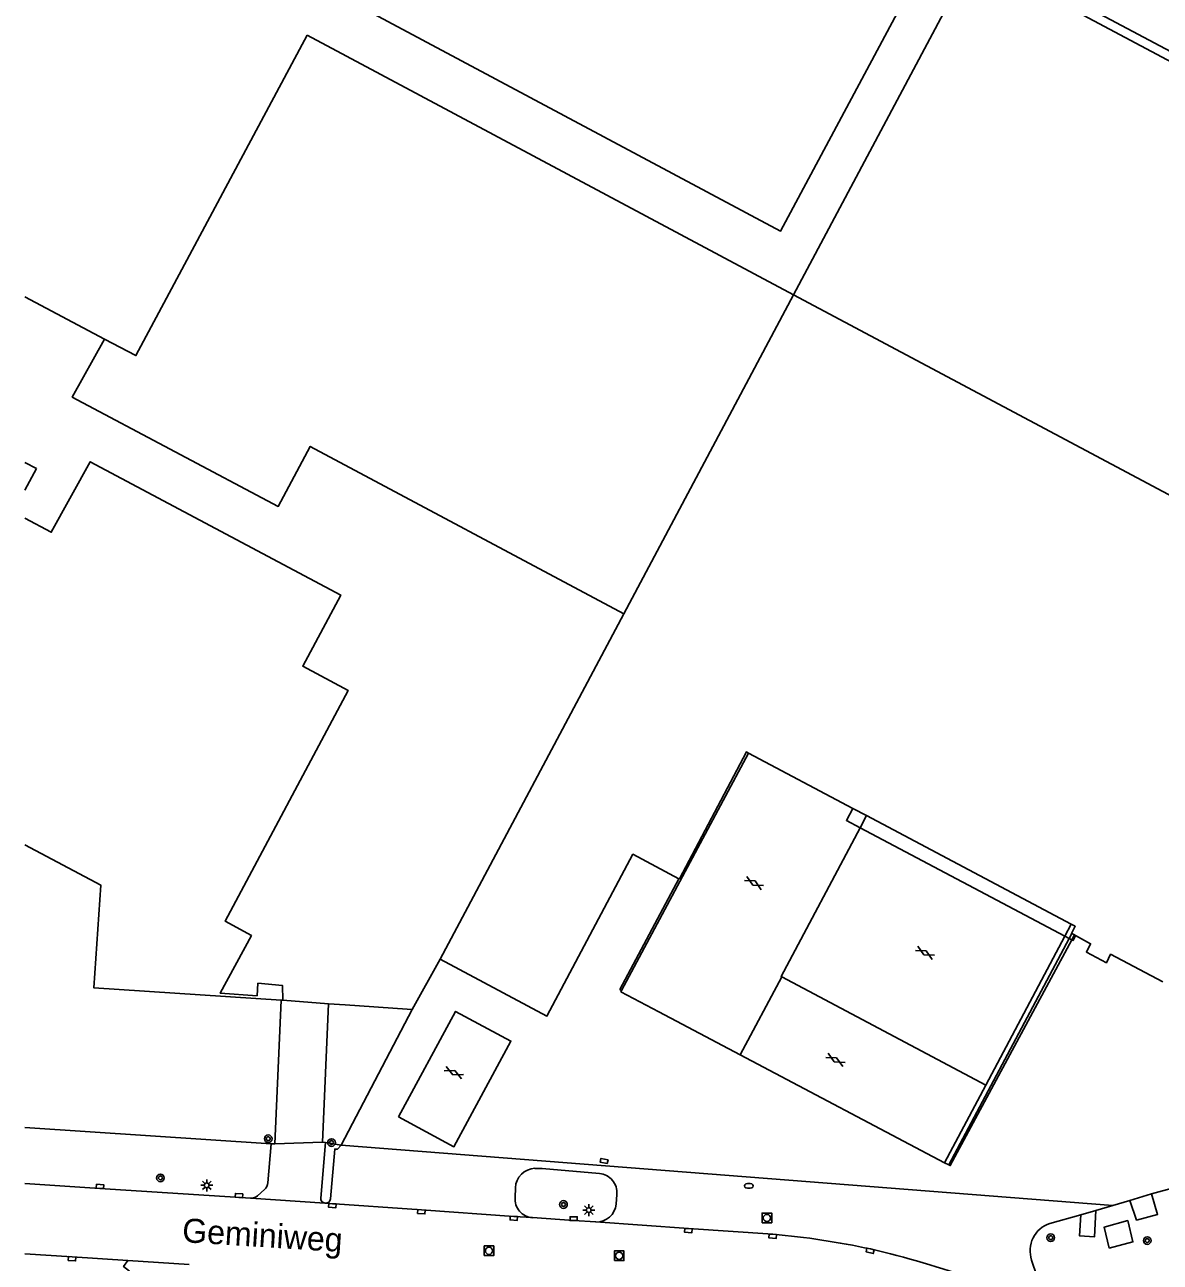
# Model space of a CAD drawing. Extents: x 135999 to 138000, y 396000 to 398501.
# Drawn here: x 136000 to 136118.3, y 398023.9 to 398152.8 of the extents above; entities that cross this region are included whole.
import ezdxf

# ---------------------------------------------------------------- set-up
doc = ezdxf.new("R2010")
doc.units = 0
for name, color, linetype in [('gg-afsc-erfafscheiding', 7, 'Continuous'), ('gg-afsc-hekwerk', 7, 'Continuous'), ('gg-afsc-muur', 7, 'Continuous'), ('gg-anno-openbare ruimte label', 7, 'Continuous'), ('gg-bbg-bijgebouw', 7, 'Continuous'), ('gg-bbg-hoofdgebouw', 7, 'Continuous'), ('gg-bbg-onder overbouw', 7, 'Continuous'), ('gg-bbg-pand overbouw', 7, 'Continuous'), ('gg-bbg-tussenscheiding', 7, 'Continuous'), ('gg-knt-verharding', 7, 'Continuous'), ('gg-knt-verharding nz', 7, 'Continuous'), ('gg-kwrk-keermuur', 7, 'Continuous'), ('gt-grn-groengrens', 7, 'Continuous'), ('gt-grn-vlakafsluiter', 7, 'Continuous'), ('gt-symb-boom', 7, 'Continuous'), ('gt-symb-brandkraan', 7, 'Continuous'), ('gt-symb-gesloten verharding', 7, 'Continuous'), ('gt-symb-kolk', 7, 'Continuous'), ('gt-symb-kolk center center', 7, 'Continuous'), ('gt-symb-lichtmast', 7, 'Continuous'), ('gt-symb-rioolschacht', 7, 'Continuous')]:
    doc.layers.add(name, color=color, linetype=linetype)

# ---------------------------------------------------------------- blocks, each defined once
blk = doc.blocks.new('gt0-BOOM')
at = {"layer": 'gt-symb-boom'}
for radius in [0.4, 0.2]:
    blk.add_circle((0, 0), radius, dxfattribs=at)
blk = doc.blocks.new('gt0-KOLK')
at = {"layer": 'gt-symb-kolk'}
blk.add_lwpolyline([(0, 0), (0.38, 0), (0.38, 0.4), (-0.38, 0.4), (-0.38, 0), (0, 0)], dxfattribs=at)
blk = doc.blocks.new('gt0-GESVH1')
at = {"layer": 'gt-symb-gesloten verharding'}
for p, q in [((-0.99, -0.26), (0.01, 0.24)), ((0.01, -0.26), (-0.99, 0.24)), ((0.01, 0.24), (1.01, -0.26)), ((1.01, 0.24), (0.01, -0.26))]:
    blk.add_line(p, q, dxfattribs=at)
blk = doc.blocks.new('gt0-BR')
at = {"layer": 'gt-symb-brandkraan'}
for centre, radius, start, end in [((-0.24, 0), 0.206, 107.5669, 252.4331), ((0.6, -2.66), 3, 106.892, 107.5669), ((0, -0.69), 0.938, 73.108, 106.892), ((-0.6, -2.66), 3, 72.4331, 73.108), ((0.24, 0), 0.206, 287.567, 72.4331), ((0.6, 2.66), 3, 252.4331, 253.108), ((0, 0.69), 0.938, 253.108, 286.8921), ((-0.6, 2.66), 3, 286.8921, 287.567)]:
    blk.add_arc(centre, radius, start, end, dxfattribs=at)
blk = doc.blocks.new('gt0-KOLKCC')
at = {"layer": 'gt-symb-kolk center center'}
blk.add_lwpolyline([(-0.38, 0.2), (0.38, 0.2), (0.38, -0.2), (-0.38, -0.2)], close=True, dxfattribs=at)
blk = doc.blocks.new('gt0-LMAST')
at = {"layer": 'gt-symb-lichtmast'}
for p, q in [((-0.18, 0.17), (-0.45, 0.44)), ((-0.01, 0.25), (-0.01, 0.62)), ((0.17, 0.17), (0.44, 0.44)), ((-0.26, 0), (-0.63, 0)), ((-0.18, -0.18), (-0.45, -0.45)), ((-0.01, -0.25), (-0.01, -0.63)), ((0.44, -0.45), (0.17, -0.18)), ((0.24, 0), (0.62, 0))]:
    blk.add_line(p, q, dxfattribs=at)
blk.add_circle((-0.01, 0), 0.25, dxfattribs=at)
blk = doc.blocks.new('gt0-RS')
at = {"layer": 'gt-symb-rioolschacht'}
blk.add_lwpolyline([(-0.5, -0.5), (0.5, -0.5), (0.5, 0.5), (-0.5, 0.5)], close=True, dxfattribs=at)
blk.add_circle((0, 0), 0.375, dxfattribs=at)

msp = doc.modelspace()

# ---------------------------------------------------------------- linework, layer by layer
at = {"layer": 'gg-afsc-erfafscheiding'}
for p, q in [((136026.05, 398036.21), (136031.02, 398036.38)), ((136113.33, 398029.79), (136032.96, 398036.09))]:
    msp.add_line(p, q, dxfattribs=at)
at = {"layer": 'gg-afsc-hekwerk'}
msp.add_line((136000, 398124.44), (136008.29, 398120.05), dxfattribs=at)
at = {"layer": 'gg-afsc-muur'}
for p, q in [((136040.34, 398050.21), (136043.28, 398055.46)), ((136026.88, 398051.18), (136031.64, 398050.82)), ((136031.64, 398050.82), (136033.38, 398050.7)), ((136033.38, 398050.7), (136039.82, 398050.25)), ((136039.82, 398050.25), (136040.34, 398050.21))]:
    msp.add_line(p, q, dxfattribs=at)
at = {"layer": 'gg-bbg-bijgebouw'}
msp.add_line((136029.4, 398151.72), (136080.08, 398124.65), dxfattribs=at)
for points in [[(136080.08, 398124.65), (136098.81, 398159.9), (136158.21, 398128.28)], [(136008.29, 398120.05), (136011.57, 398118.33), (136029.4, 398151.72)], [(136062.39, 398091.42), (136029.73, 398108.87), (136026.41, 398102.62), (136004.95, 398114.02), (136008.29, 398120.05)]]:
    msp.add_lwpolyline(points, dxfattribs=at)
at = {"layer": 'gg-bbg-hoofdgebouw'}
for p, q in [((136000, 398107.21), (136001.21, 398106.56)), ((136000, 398104.33), (136001.21, 398106.56)), ((136043.28, 398055.46), (136062.39, 398091.42)), ((136086.24, 398071.17), (136075.37, 398076.93)), ((136026.72, 398051.19), (136026.88, 398051.18))]:
    msp.add_line(p, q, dxfattribs=at)
for points in [[(136037, 398187.29), (136092.74, 398157.55), (136078.71, 398131.29), (136023, 398161.08)], [(136177.55, 398164.23), (136167.76, 398145.6), (136164.15, 398147.56), (136155.32, 398130.9), (136084.58, 398168.48)], [(136000, 398101.4), (136002.76, 398099.93), (136006.83, 398107.28), (136032.91, 398093.38), (136028.95, 398085.97), (136033.68, 398083.45), (136020.86, 398059.43), (136023.61, 398057.92), (136020.36, 398051.9), (136024.2, 398051.64), (136024.29, 398052.95), (136026.83, 398052.73), (136026.88, 398051.18)], [(136075.37, 398076.93), (136075.17, 398077.04), (136068.18, 398063.81), (136068.14, 398063.83)], [(136000, 398067.38), (136007.91, 398063.17), (136007.2, 398052.47), (136026.72, 398051.19)], [(136068.14, 398063.83), (136063.34, 398066.39), (136054.38, 398049.53), (136043.28, 398055.46)], [(136118.54, 398053.1), (136113.1, 398055.97), (136112.65, 398055.09), (136110.57, 398056.19), (136111.01, 398057.07), (136109.45, 398057.91)]]:
    msp.add_lwpolyline(points, dxfattribs=at)
at = {"layer": 'gg-bbg-onder overbouw'}
for p, q in [((136087.67, 398070.41), (136086.24, 398071.17)), ((136108.99, 398059.11), (136087.67, 398070.41)), ((136109.32, 398057.98), (136109.05, 398058.12)), ((136109.45, 398057.91), (136109.32, 398057.98))]:
    msp.add_line(p, q, dxfattribs=at)
msp.add_lwpolyline([(136109.05, 398058.12), (136109.02, 398058.14), (136109.42, 398058.88), (136108.99, 398059.11)], dxfattribs=at)
at = {"layer": 'gg-bbg-pand overbouw'}
for p, q in [((136087, 398069.15), (136108.33, 398057.85)), ((136108.33, 398057.85), (136108.78, 398057.61)), ((136108.78, 398057.61), (136109.05, 398057.47))]:
    msp.add_line(p, q, dxfattribs=at)
for points in [[(136086.24, 398071.17), (136085.57, 398069.91), (136087, 398069.15)], [(136109.05, 398057.47), (136109.18, 398057.4), (136109.45, 398057.91)]]:
    msp.add_lwpolyline(points, dxfattribs=at)
at = {"layer": 'gg-bbg-tussenscheiding'}
for p, q in [((136062.39, 398091.42), (136080.08, 398124.65)), ((136080.08, 398124.65), (136139.66, 398092.93))]:
    msp.add_line(p, q, dxfattribs=at)
at = {"layer": 'gg-knt-verharding'}
for p, q in [((136108.33, 398057.85), (136108.99, 398059.11)), ((136100.1, 398042.33), (136108.33, 398057.85)), ((136026.05, 398036.21), (136026.72, 398051.19)), ((136031.64, 398050.82), (136031.02, 398036.38)), ((136032.96, 398036.09), (136040.34, 398050.21)), ((136074.51, 398045.5), (136095.79, 398034.24)), ((136095.79, 398034.24), (136100.1, 398042.33)), ((136031.32, 398036.35), (136030.83, 398030.56)), ((136031.02, 398036.38), (136031.32, 398036.35)), ((136025.31, 398032.16), (136025.65, 398036.23)), ((136025.65, 398036.23), (136026.05, 398036.21)), ((136095.79, 398034.24), (136096.23, 398034.04)), ((136024.24, 398030.82), (136024.98, 398031.47)), ((136051.08, 398030.64), (136051.11, 398031.63)), ((136117.36, 398031.01), (136119.77, 398031.68)), ((136023.53, 398030.55), (136031.27, 398030.04)), ((136031.3, 398030.03), (136031.27, 398030.04)), ((136061.67, 398030.94), (136061.58, 398029.93)), ((136113.33, 398029.79), (136115.09, 398030.3)), ((136117.36, 398031.01), (136115.09, 398030.3)), ((136106.76, 398027.93), (136110.01, 398028.84)), ((136111.57, 398029.27), (136110.01, 398028.84)), ((136111.57, 398029.27), (136113.33, 398029.79)), ((136010.74, 398024.07), (136017.13, 398023.65)), ((136106.48, 398019.36), (136104.87, 398024.11))]:
    msp.add_line(p, q, dxfattribs=at)
for points in [[(136074.51, 398045.5), (136066.03, 398049.97), (136062.1, 398052.07), (136062.17, 398052.21)], [(136038.93, 398039.02), (136044.7, 398035.92), (136050.64, 398046.92), (136044.87, 398050.02), (136038.93, 398039.02)], [(136031.84, 398030.49), (136032.28, 398035.68), (136032.58, 398035.67), (136032.96, 398036.09)], [(136053.14, 398033.66), (136053.89, 398033.65), (136059.86, 398033.12)], [(136000, 398032.08), (136007.83, 398031.58), (136023.53, 398030.55)], [(136031.3, 398030.03), (136041.32, 398029.34), (136050.95, 398028.66), (136052.88, 398028.53)], [(136115.09, 398030.3), (136115.8, 398028.27), (136117.99, 398028.87), (136117.36, 398031.01)], [(136110.01, 398028.84), (136109.87, 398026.62), (136111.43, 398026.54), (136111.57, 398029.27)], [(136052.88, 398028.53), (136057.17, 398028.23), (136059.49, 398028.08)], [(136059.49, 398028.08), (136069.13, 398027.39), (136077.92, 398026.8)], [(136112.96, 398025.34), (136112.43, 398027.55), (136114.88, 398028.23), (136115.41, 398026.01), (136112.96, 398025.34)], [(136000, 398024.77), (136004.94, 398024.45), (136010.74, 398024.07)], [(136010.74, 398024.07), (136010.3, 398023.44), (136010.9, 398022.95), (136010.83, 398022.48)]]:
    msp.add_lwpolyline(points, dxfattribs=at)
for centre, radius, start, end in [((136053.23, 398031.54), 2.13, 92.61, 177.4183), ((136059.7, 398031.16), 1.97, 353.8366, 85.474), ((136024.23, 398032.26), 1.09, 313.3448, 354.8537), ((136023.55, 398031.59), 1.04, 268.8415, 312.06), ((136031.32, 398030.53), 0.493, 175.623, 264.772), ((136031.33, 398030.54), 0.509, 266.2749, 353.8156), ((136053.02, 398030.47), 1.95, 175.1729, 265.783), ((136059.54, 398030.13), 2.06, 268.6287, 354.4174), ((136107.72, 398025.08), 3.01, 108.5979, 198.7895), ((136070.92, 397945.66), 81.44, 77.829, 85.0676), ((136062.69, 397918.38), 109.87, 70.7185, 76.6324)]:
    msp.add_arc(centre, radius, start, end, dxfattribs=at)
at = {"layer": 'gg-knt-verharding nz'}
for p, q in [((136087, 398069.15), (136087.67, 398070.41)), ((136074.51, 398045.5), (136078.85, 398053.63)), ((136078.85, 398053.63), (136100.1, 398042.33))]:
    msp.add_line(p, q, dxfattribs=at)
msp.add_lwpolyline([(136078.85, 398053.63), (136078.78, 398053.65), (136087, 398069.15)], dxfattribs=at)
at = {"layer": 'gg-kwrk-keermuur'}
for p, q in [((136075.37, 398076.93), (136062.17, 398052.21)), ((136108.78, 398057.61), (136096.23, 398034.04)), ((136109.05, 398058.12), (136108.78, 398057.61)), ((136109.05, 398057.47), (136109.32, 398057.98))]:
    msp.add_line(p, q, dxfattribs=at)
for points in [[(136062.17, 398052.21), (136061.99, 398052.3), (136068.14, 398063.83)], [(136096.23, 398034.04), (136096.4, 398033.95), (136109.05, 398057.47)]]:
    msp.add_lwpolyline(points, dxfattribs=at)
at = {"layer": 'gt-grn-groengrens'}
msp.add_line((136031.32, 398036.35), (136032.96, 398036.09), dxfattribs=at)
at = {"layer": 'gt-grn-vlakafsluiter'}
msp.add_line((136000, 398037.93), (136025.65, 398036.23), dxfattribs=at)

# ---------------------------------------------------------------- block references
at = {"layer": 'gt-symb-boom'}
for p in [(136025.36, 398036.75), (136031.95, 398036.35), (136014.13, 398032.67), (136056.11, 398029.9), (136106.86, 398026.44), (136116.91, 398026.14)]:
    msp.add_blockref('gt0-BOOM', p, dxfattribs=at)
at = {"layer": 'gt-symb-brandkraan'}
msp.add_blockref('gt0-BR', (136075.41, 398031.84), dxfattribs=at)
at = {"layer": 'gt-symb-gesloten verharding'}
for p, rotation in [((136075.95, 398063.4), -28.487007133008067), ((136093.76, 398056.13), -28.487007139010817), ((136084.43, 398044.98), -28.48700713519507), ((136044.68, 398043.65), -24.89920052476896)]:
    msp.add_blockref('gt0-GESVH1', p, dxfattribs=dict(at, rotation=rotation))
at = {"layer": 'gt-symb-kolk'}
for p, rotation in [((136007.83, 398031.58), -3.4238023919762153), ((136022.3, 398030.63), -3.4238023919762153), ((136032.05, 398029.98), 176.05870043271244), ((136041.32, 398029.34), 176.05870043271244), ((136050.95, 398028.66), 176.05870043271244), ((136069.13, 398027.39), 176.0587004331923), ((136077.92, 398026.8), 176.05870043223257), ((136088.09, 398025.27), 166.52937593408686), ((136004.94, 398024.45), 176.26107557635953)]:
    msp.add_blockref('gt0-KOLK', p, dxfattribs=dict(at, rotation=rotation))
msp.add_blockref('gt0-KOLK', (136057.17, 398028.23), dxfattribs=at)
at = {"layer": 'gt-symb-kolk center center', "rotation": 167.93725397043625}
msp.add_blockref('gt0-KOLKCC', (136060.34, 398034.43), dxfattribs=at)
at = {"layer": 'gt-symb-lichtmast'}
for p in [(136018.96, 398031.9), (136058.75, 398029.32)]:
    msp.add_blockref('gt0-LMAST', p, dxfattribs=at)
at = {"layer": 'gt-symb-rioolschacht'}
for p in [(136077.3, 398028.5), (136048.35, 398025.08), (136061.91, 398024.56)]:
    msp.add_blockref('gt0-RS', p, dxfattribs=at)

# ---------------------------------------------------------------- texts
at = {"layer": 'gg-anno-openbare ruimte label'}
msp.add_text('Geminiweg', height=2.5, rotation=356.4, dxfattribs=at).set_placement((136016.34, 398025.99))

doc.saveas('drawing.dxf')
